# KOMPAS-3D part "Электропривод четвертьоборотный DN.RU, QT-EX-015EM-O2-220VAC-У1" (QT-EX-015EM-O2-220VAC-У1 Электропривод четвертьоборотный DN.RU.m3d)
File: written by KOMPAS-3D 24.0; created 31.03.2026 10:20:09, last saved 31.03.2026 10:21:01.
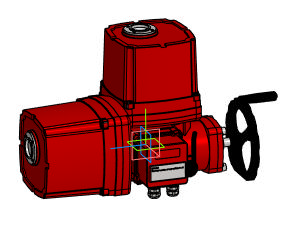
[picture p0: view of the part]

Document properties: Автор: DN.RU; Полное имя файла: D:\PROJECT CAD\DN.RU\...194\QT-EX-xEM-O2-x-У1 Электропривод четвертьоборотный DN.ru\QT-EX-015EM-O2-220VAC-У1\QT-EX-015EM-O2-220VAC-У1 Электропривод четвертьоборотный DN.RU.m3d

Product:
- Body: Твердое тело1  | qty 1
    Масса: 65.658095
- Part/product: Электропривод четвертьоборотный DN.RU  | designation QT-EX-015EM-O2-220VAC-У1
    Масса: 15
    Раздел спецификации: Прочие изделия
    Комментарий: D300-04902
    Примечание: D300-04902
    additional columns: Сталь

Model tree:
1. Твердое тело1  (labels: Твердое тело1)

Expressions: QT-EX-015EM-O2-220VAC-У1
